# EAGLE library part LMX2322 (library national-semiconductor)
PLLatinumTM 2.0 GHz Frequency Synthesizer for RF Personal Communications Source: LMX2322.pdf
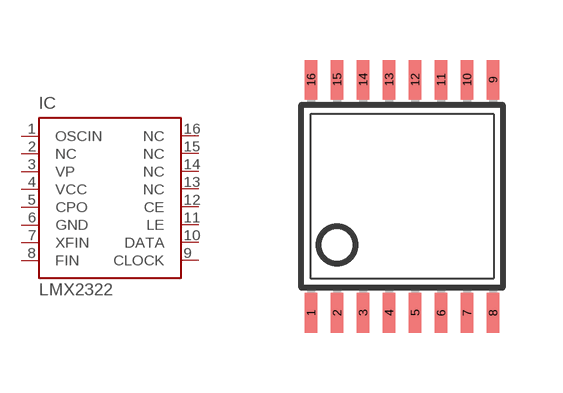
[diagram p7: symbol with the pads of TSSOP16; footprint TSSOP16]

Designator prefix IC

## LMX2322 (OC_FARNELL: unknown; OC_NEWARK: unknown)  [TSSOP16]
1  OSCIN  in
2  NC  nc
3  VP  pwr
4  VCC  pwr
5  CPO  out
6  GND  pwr
7  XFIN  in
8  FIN  in
9  CLOCK  in
10  DATA  in
11  LE  in
12  CE  in
13  NC  nc
14  NC  nc
15  NC  nc
16  NC  nc

## Footprint TSSOP16 (pad centres in mm)
Thin Shrink Small Outline Plastic 16
smd 0.305 x 0.991: 1 -2.275,-2.918; 2 -1.625,-2.918; 3 -0.975,-2.918; 4 -0.325,-2.918; 5 0.325,-2.918; 6 0.975,-2.918; 7 1.625,-2.918; 8 2.275,-2.918; 9 2.275,2.918; 10 1.625,2.918; 11 0.975,2.918; 12 0.325,2.918; 13 -0.325,2.918; 14 -0.975,2.918; 15 -1.625,2.918; 16 -2.275,2.918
